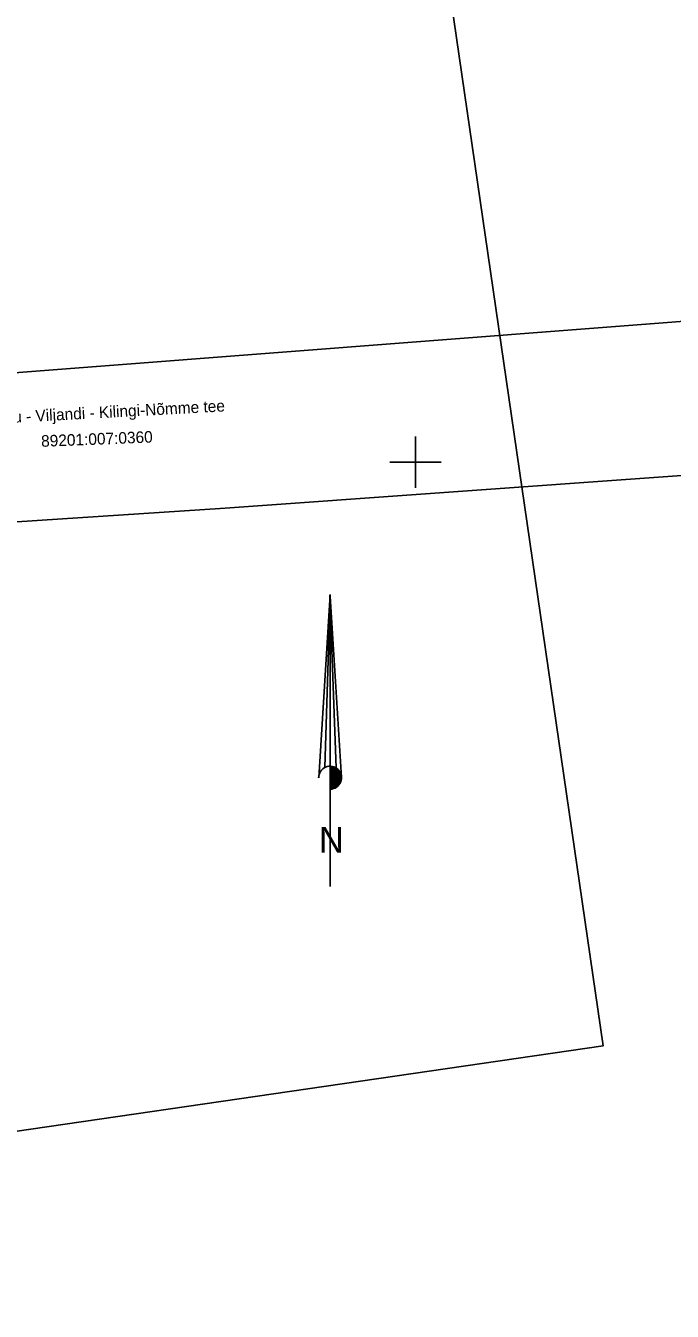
# Model space of a CAD drawing. Extents: x 604066 to 604956, y 6473634 to 6474346.
# Drawn here: x 604719.6 to 604770, y 6473633.8 to 6473734 of the extents above; entities that cross this region are included whole.
import ezdxf

# ---------------------------------------------------------------- set-up
doc = ezdxf.new("R2010")
doc.units = 0
for name, color, linetype in [('PIIR', 7, 'Continuous'), ('VORK', 7, 'Continuous'), ('VORMISTUS', 7, 'Continuous')]:
    doc.layers.add(name, color=color, linetype=linetype)

msp = doc.modelspace()

# ---------------------------------------------------------------- linework, layer by layer
at = {"layer": 'PIIR'}
for points in [[(604833.54, 6473909.5), (604897.39, 6473936.49), (604953.49, 6473960.24), (604956.07, 6473961.29), (604940.8, 6473724.06), (604687.73, 6473704.56), (604680.66, 6473747.8), (604821.94, 6473844.68)], [(604687.73, 6473704.56), (604940.8, 6473724.06), (604940.18, 6473714.53), (604940.07, 6473712.83), (604892.72, 6473708.69), (604839.74, 6473704.2), (604787.09, 6473700.12), (604735.18, 6473696.42), (604689.63, 6473693.43), (604689.38, 6473694.91)]]:
    msp.add_lwpolyline(points, close=True, dxfattribs=at)
at = {"layer": 'VORK'}
for p, q in [((604750, 6473702), (604750, 6473698)), ((604748, 6473700), (604752, 6473700))]:
    msp.add_line(p, q, dxfattribs=at)
at = {"layer": 'VORMISTUS'}
msp.add_lwpolyline([(604563.86, 6474037.6), (604705.86, 6474058.26), (604764.62, 6473654.52), (604622.61, 6473633.85)], close=True, dxfattribs=at)
for points in [[(604743.35, 6473689.68), (604742.46, 6473675.41)], [(604743.35, 6473689.58), (604742.93, 6473676.21)], [(604743.34, 6473689.63), (604743.81, 6473676.18)], [(604743.35, 6473689.68), (604743.35, 6473666.93)], [(604743.35, 6473689.57), (604744.25, 6473675.44)], [(604743.35, 6473676.21), (604743.77, 6473676.21)], [(604743.35, 6473676.1), (604743.92, 6473676.1)], [(604743.35, 6473676), (604744.01, 6473676)], [(604743.42, 6473674.54), (604743.42, 6473676.3)], [(604743.52, 6473674.56), (604743.52, 6473676.29)], [(604743.63, 6473674.57), (604743.63, 6473676.26)], [(604743.73, 6473674.62), (604743.73, 6473676.22)], [(604743.83, 6473674.68), (604743.83, 6473676.18)], [(604743.93, 6473674.76), (604743.93, 6473676.09)], [(604744.04, 6473674.86), (604744.04, 6473675.97)], [(604743.35, 6473675.9), (604744.09, 6473675.9)], [(604743.35, 6473675.79), (604744.15, 6473675.79)], [(604743.35, 6473675.69), (604744.19, 6473675.69)], [(604743.35, 6473675.59), (604744.22, 6473675.59)], [(604743.35, 6473675.48), (604744.23, 6473675.48)], [(604743.35, 6473675.38), (604744.24, 6473675.38)], [(604743.35, 6473675.28), (604744.22, 6473675.28)], [(604743.35, 6473675.18), (604744.2, 6473675.18)], [(604743.35, 6473675.07), (604744.16, 6473675.07)], [(604743.35, 6473674.97), (604744.11, 6473674.97)], [(604744.14, 6473675.03), (604744.14, 6473675.83)], [(604743.35, 6473674.87), (604744.04, 6473674.87)], [(604743.35, 6473674.76), (604743.94, 6473674.76)], [(604743.35, 6473674.66), (604743.8, 6473674.66)], [(604743.35, 6473674.56), (604743.54, 6473674.56)]]:
    msp.add_lwpolyline(points, dxfattribs=at)
msp.add_arc((604743.35, 6473675.42), 0.894, 270.3348, 180.6244, dxfattribs=at)

# ---------------------------------------------------------------- texts
at = {"layer": 'PIIR'}
for s, rotation, p in [('92 Tartu - Viljandi - Kilingi-Nõmme tee', 3.0938, (604714.87, 6473702.86)), ('89201:007:0360', 2.2566, (604720.85, 6473701.19))]:
    msp.add_text(s, height=0.9, rotation=rotation, dxfattribs=at).set_placement(p)
at = {"layer": 'VORMISTUS'}
msp.add_text('N', height=2, dxfattribs=at).set_placement((604742.48, 6473669.59))

doc.saveas('drawing.dxf')
